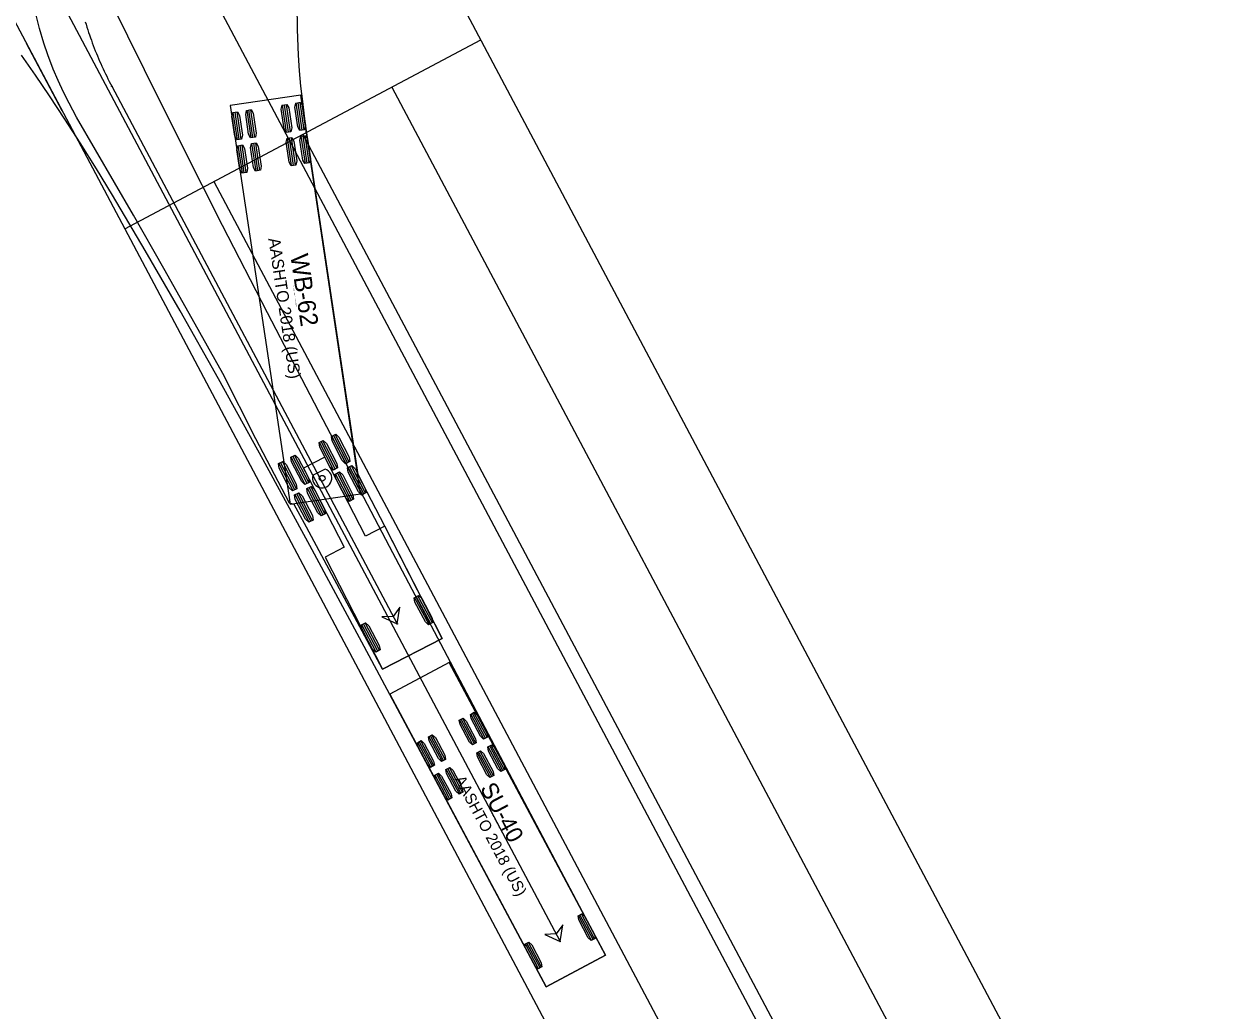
# Model space of a CAD drawing. Extents: x 2297881 to 2300600, y 559917 to 564426.
# Drawn here: x 2299397.2 to 2299541.4, y 561683.1 to 561800.6 of the extents above; entities that cross this region are included whole.
import ezdxf

# ---------------------------------------------------------------- set-up
doc = ezdxf.new("R2010")
doc.units = 0
for name, color, linetype in [('GE_X_Alignment', 7, 'Continuous'), ('PM_P_CL_Pass_Proh_Lt', 7, 'Continuous'), ('PM_P_Dotted_Line', 7, 'Continuous'), ('PM_P_Edge_Line', 7, 'Continuous'), ('PM_P_Lane_Line', 7, 'Continuous'), ('SC_Scratch1', 7, 'Continuous'), ('SN_X_Public', 7, 'Continuous'), ('SV_X_Control_Cells_Found', 7, 'Continuous')]:
    doc.layers.add(name, color=color, linetype=linetype)

msp = doc.modelspace()

# ---------------------------------------------------------------- linework, layer by layer
at = {"layer": 'GE_X_Alignment'}
msp.add_line((2299396.64, 561847.4), (2299991.21, 560726.85), dxfattribs=at)
at = {"layer": 'PM_P_CL_Pass_Proh_Lt'}
msp.add_line((2299430.41, 561787.49), (2299568.68, 561526.9), dxfattribs=at)
at = {"layer": 'PM_P_Dotted_Line'}
msp.add_line((2299441.01, 561793.11), (2299579.28, 561532.52), dxfattribs=at)
at = {"layer": 'PM_P_Edge_Line'}
for p, q in [((2299407.66, 561793.21), (2299441.64, 561729.21)), ((2299430.18, 561792.17), (2299421.77, 561790.91)), ((2299421.77, 561790.91), (2299428.88, 561743.44)), ((2299428.48, 561787.72), (2299427.99, 561790.99)), ((2299428.71, 561787.76), (2299428.22, 561791.02)), ((2299428.94, 561787.79), (2299428.45, 561791.05)), ((2299430.11, 561787.97), (2299429.63, 561791.23)), ((2299430.34, 561788), (2299429.85, 561791.26)), ((2299430.57, 561788.03), (2299430.08, 561791.3)), ((2299437.29, 561744.7), (2299430.18, 561792.17)), ((2299422.61, 561786.84), (2299422.13, 561790.11)), ((2299422.84, 561786.88), (2299422.35, 561790.14)), ((2299423.07, 561786.91), (2299422.58, 561790.18)), ((2299424.25, 561787.09), (2299423.76, 561790.35)), ((2299424.47, 561787.12), (2299423.98, 561790.39)), ((2299424.7, 561787.16), (2299424.21, 561790.42)), ((2299425.29, 561783.2), (2299424.8, 561786.46)), ((2299429.07, 561783.77), (2299428.59, 561787.03)), ((2299429.3, 561783.8), (2299428.81, 561787.06)), ((2299429.53, 561783.83), (2299429.04, 561787.1)), ((2299430.71, 561784.01), (2299430.22, 561787.27)), ((2299430.93, 561784.04), (2299430.44, 561787.31)), ((2299431.16, 561784.08), (2299430.67, 561787.34)), ((2299423.21, 561782.89), (2299422.72, 561786.15)), ((2299423.43, 561782.92), (2299422.94, 561786.19)), ((2299423.66, 561782.96), (2299423.17, 561786.22)), ((2299424.84, 561783.13), (2299424.35, 561786.4)), ((2299425.06, 561783.17), (2299424.58, 561786.43)), ((2299434.07, 561747.54), (2299432.39, 561750.8)), ((2299434.27, 561747.65), (2299432.59, 561750.91)), ((2299434.48, 561747.75), (2299432.8, 561751.01)), ((2299435.54, 561748.3), (2299433.86, 561751.56)), ((2299435.74, 561748.4), (2299434.06, 561751.66)), ((2299435.94, 561748.51), (2299434.26, 561751.77)), ((2299430.7, 561745.81), (2299429.03, 561749.07)), ((2299430.91, 561745.92), (2299429.23, 561749.18)), ((2299431.11, 561746.02), (2299429.43, 561749.28)), ((2299433.03, 561749.07), (2299430.48, 561747.76)), ((2299437.88, 561739.64), (2299433.03, 561749.07)), ((2299429.24, 561745.06), (2299427.56, 561748.32)), ((2299429.44, 561745.16), (2299427.76, 561748.42)), ((2299429.64, 561745.27), (2299427.97, 561748.53)), ((2299430.48, 561747.76), (2299435.33, 561738.33)), ((2299433.06, 561747.63), (2299431.62, 561746.89)), ((2299437.46, 561744.56), (2299435.78, 561747.82)), ((2299437.66, 561744.67), (2299435.98, 561747.93)), ((2299437.86, 561744.77), (2299436.19, 561748.03)), ((2299435.99, 561743.81), (2299434.31, 561747.07)), ((2299436.19, 561743.91), (2299434.52, 561747.17)), ((2299436.4, 561744.02), (2299434.72, 561747.28)), ((2299428.88, 561743.44), (2299437.29, 561744.7)), ((2299431.36, 561741.43), (2299429.69, 561744.69)), ((2299431.57, 561741.53), (2299429.89, 561744.79)), ((2299432.63, 561742.08), (2299430.95, 561745.34)), ((2299432.83, 561742.18), (2299431.15, 561745.44)), ((2299433.03, 561742.29), (2299431.36, 561745.55)), ((2299437.29, 561744.7), (2299437.29, 561744.7)), ((2299431.16, 561741.32), (2299429.48, 561744.58)), ((2299440.16, 561740.82), (2299437.88, 561739.64)), ((2299447.02, 561727.48), (2299440.16, 561740.82)), ((2299435.33, 561738.33), (2299433.05, 561737.16)), ((2299433.05, 561737.16), (2299439.91, 561723.82)), ((2299445.44, 561729.11), (2299443.72, 561732.34)), ((2299445.64, 561729.21), (2299443.92, 561732.45)), ((2299445.84, 561729.32), (2299444.12, 561732.56)), ((2299439.15, 561725.85), (2299437.43, 561729.09)), ((2299439.35, 561725.96), (2299437.63, 561729.2)), ((2299439.55, 561726.07), (2299437.83, 561729.31)), ((2299439.91, 561723.82), (2299447.02, 561727.48)), ((2299447.02, 561727.48), (2299447.02, 561727.48))]:
    msp.add_line(p, q, dxfattribs=at)
for points in [[(2299429.7, 561803.02), (2299429.72, 561799.96), (2299429.86, 561796.9), (2299429.99, 561795.07), (2299430.15, 561793.24), (2299430.35, 561791.41), (2299430.66, 561788.97), (2299436.96, 561746.97), (2299440.14, 561740.86), (2299447.02, 561727.48), (2299439.91, 561723.82), (2299430.85, 561740.71), (2299429.38, 561743.43), (2299428.81, 561743.58), (2299424.82, 561751.25), (2299420.87, 561759.02), (2299417.24, 561765.54), (2299413.87, 561771.51), (2299410.23, 561777.85), (2299403.47, 561789.53), (2299402.56, 561791.19), (2299401.89, 561792.53), (2299401.27, 561793.89), (2299400.69, 561795.25), (2299400.04, 561796.97), (2299399.57, 561798.35), (2299399.05, 561800.1), (2299398.6, 561801.85)], [(2299404.49, 561800.9), (2299404.59, 561800.59), (2299404.69, 561800.27), (2299404.79, 561799.95), (2299404.89, 561799.63), (2299405, 561799.32), (2299405.11, 561799), (2299405.22, 561798.69), (2299405.33, 561798.38), (2299405.45, 561798.06), (2299405.57, 561797.75), (2299405.69, 561797.44), (2299405.82, 561797.13), (2299405.94, 561796.82), (2299406.07, 561796.52), (2299406.2, 561796.21), (2299406.34, 561795.91), (2299406.48, 561795.6), (2299406.61, 561795.3), (2299406.76, 561795), (2299406.9, 561794.7), (2299407.05, 561794.4), (2299407.2, 561794.1), (2299407.35, 561793.8), (2299407.5, 561793.51), (2299407.66, 561793.21)], [(2299441.64, 561729.21), (2299441.97, 561731.18), (2299441.17, 561730.09), (2299439.82, 561730.04), (2299441.64, 561729.21)]]:
    msp.add_lwpolyline(points, dxfattribs=at)
for points in [[(2299428.99, 561787.8), (2299428.43, 561787.71), (2299428.19, 561788.15), (2299427.84, 561790.5), (2299427.94, 561790.98), (2299428.5, 561791.06), (2299428.74, 561790.63), (2299429.09, 561788.28)], [(2299430.62, 561788.04), (2299430.06, 561787.96), (2299429.82, 561788.39), (2299429.47, 561790.74), (2299429.57, 561791.22), (2299430.14, 561791.31), (2299430.37, 561790.87), (2299430.73, 561788.53)], [(2299423.12, 561786.92), (2299422.56, 561786.84), (2299422.32, 561787.27), (2299421.97, 561789.62), (2299422.07, 561790.1), (2299422.64, 561790.18), (2299422.87, 561789.75), (2299423.23, 561787.4)], [(2299424.76, 561787.16), (2299424.19, 561787.08), (2299423.95, 561787.51), (2299423.6, 561789.86), (2299423.7, 561790.34), (2299424.27, 561790.43), (2299424.51, 561790), (2299424.86, 561787.65)], [(2299425.35, 561783.21), (2299424.78, 561783.12), (2299424.54, 561783.56), (2299424.19, 561785.91), (2299424.29, 561786.39), (2299424.86, 561786.47), (2299425.1, 561786.04), (2299425.45, 561783.69)], [(2299429.58, 561783.84), (2299429.02, 561783.76), (2299428.78, 561784.19), (2299428.43, 561786.54), (2299428.53, 561787.02), (2299429.1, 561787.11), (2299429.33, 561786.67), (2299429.69, 561784.32)], [(2299431.22, 561784.09), (2299430.65, 561784), (2299430.41, 561784.43), (2299430.06, 561786.78), (2299430.16, 561787.27), (2299430.73, 561787.35), (2299430.97, 561786.92), (2299431.32, 561784.57)], [(2299423.72, 561782.96), (2299423.15, 561782.88), (2299422.91, 561783.31), (2299422.56, 561785.66), (2299422.66, 561786.14), (2299423.23, 561786.23), (2299423.47, 561785.8), (2299423.82, 561783.45)], [(2299434.53, 561747.78), (2299434.02, 561747.52), (2299433.63, 561747.89), (2299432.42, 561750.24), (2299432.34, 561750.78), (2299432.85, 561751.04), (2299433.24, 561750.66), (2299434.44, 561748.31)], [(2299435.99, 561748.53), (2299435.48, 561748.27), (2299435.1, 561748.65), (2299433.89, 561751), (2299433.81, 561751.53), (2299434.32, 561751.79), (2299434.7, 561751.42), (2299435.91, 561749.07)], [(2299431.16, 561746.05), (2299430.65, 561745.79), (2299430.27, 561746.16), (2299429.06, 561748.51), (2299428.98, 561749.05), (2299429.48, 561749.31), (2299429.87, 561748.93), (2299431.08, 561746.58)], [(2299429.7, 561745.29), (2299429.19, 561745.03), (2299428.8, 561745.41), (2299427.59, 561747.76), (2299427.51, 561748.29), (2299428.02, 561748.55), (2299428.41, 561748.17), (2299429.61, 561745.83)], [(2299437.92, 561744.8), (2299437.41, 561744.54), (2299437.02, 561744.91), (2299435.81, 561747.26), (2299435.73, 561747.8), (2299436.24, 561748.06), (2299436.63, 561747.68), (2299437.83, 561745.33)], [(2299436.45, 561744.04), (2299435.94, 561743.78), (2299435.55, 561744.16), (2299434.34, 561746.51), (2299434.26, 561747.04), (2299434.77, 561747.3), (2299435.16, 561746.93), (2299436.37, 561744.58)], [(2299431.62, 561741.56), (2299431.11, 561741.3), (2299430.72, 561741.67), (2299429.51, 561744.02), (2299429.43, 561744.56), (2299429.94, 561744.82), (2299430.33, 561744.44), (2299431.54, 561742.09)], [(2299433.08, 561742.31), (2299432.58, 561742.05), (2299432.19, 561742.43), (2299430.98, 561744.78), (2299430.9, 561745.31), (2299431.41, 561745.57), (2299431.79, 561745.2), (2299433, 561742.85)], [(2299445.89, 561729.35), (2299445.39, 561729.08), (2299445, 561729.45), (2299443.76, 561731.78), (2299443.67, 561732.32), (2299444.18, 561732.59), (2299444.57, 561732.21), (2299445.81, 561729.88)], [(2299441.64, 561729.21), (2299441.97, 561731.18), (2299441.17, 561730.09), (2299439.82, 561730.04)], [(2299439.6, 561726.1), (2299439.1, 561725.83), (2299438.7, 561726.2), (2299437.47, 561728.53), (2299437.38, 561729.07), (2299437.88, 561729.33), (2299438.28, 561728.96), (2299439.51, 561726.63)]]:
    msp.add_lwpolyline(points, close=True, dxfattribs=at)
for centre, radius in [((2299407.66, 561793.21), 0.0417), ((2299432.71, 561746.54), 0.34), ((2299441.64, 561729.21), 0.0417)]:
    msp.add_circle(centre, radius, dxfattribs=at)
msp.add_arc((2299432.71, 561746.54), 1.14, 162.2344, 72.2344, dxfattribs=at)
at = {"layer": 'PM_P_Lane_Line'}
for p, q in [((2299419.39, 561859.47), (2299927.35, 560902.13)), ((2299376.99, 561836.97), (2299547.48, 561515.65))]:
    msp.add_line(p, q, dxfattribs=at)
at = {"layer": 'SC_Scratch1'}
for p, q in [((2299401.75, 561790.3), (2299397.49, 561798.32)), ((2299409.21, 561776.24), (2299451.61, 561798.74))]:
    msp.add_line(p, q, dxfattribs=at)
at = {"layer": 'SN_X_Public'}
for p, q in [((2299397.07, 561811.91), (2299461.04, 561691.4)), ((2299447.84, 561724.6), (2299440.78, 561720.83)), ((2299466.45, 561689.76), (2299447.84, 561724.6)), ((2299440.78, 561720.83), (2299459.39, 561685.99)), ((2299450.66, 561714.81), (2299449.09, 561717.75)), ((2299450.84, 561714.9), (2299449.27, 561717.85)), ((2299451.03, 561715), (2299449.46, 561717.94)), ((2299451.98, 561715.51), (2299450.41, 561718.45)), ((2299452.17, 561715.61), (2299450.6, 561718.55)), ((2299452.35, 561715.71), (2299450.78, 561718.65)), ((2299447.17, 561712.94), (2299445.6, 561715.88)), ((2299447.35, 561713.04), (2299445.78, 561715.98)), ((2299445.66, 561712.14), (2299444.09, 561715.08)), ((2299445.85, 561712.24), (2299444.28, 561715.18)), ((2299446.03, 561712.33), (2299444.46, 561715.27)), ((2299446.99, 561712.84), (2299445.42, 561715.78)), ((2299454.06, 561711.63), (2299452.49, 561714.57)), ((2299454.24, 561711.73), (2299452.67, 561714.67)), ((2299454.42, 561711.83), (2299452.85, 561714.77)), ((2299452.73, 561710.93), (2299451.16, 561713.87)), ((2299452.92, 561711.02), (2299451.35, 561713.96)), ((2299453.1, 561711.12), (2299451.53, 561714.06)), ((2299449.06, 561708.96), (2299447.49, 561711.9)), ((2299449.24, 561709.06), (2299447.67, 561712)), ((2299449.43, 561709.16), (2299447.86, 561712.1)), ((2299447.73, 561708.26), (2299446.16, 561711.2)), ((2299447.92, 561708.35), (2299446.35, 561711.29)), ((2299448.1, 561708.45), (2299446.53, 561711.39)), ((2299464.79, 561691.52), (2299463.23, 561694.46)), ((2299464.98, 561691.62), (2299463.42, 561694.56)), ((2299465.16, 561691.71), (2299463.6, 561694.66)), ((2299458.47, 561688.14), (2299456.91, 561691.09)), ((2299458.66, 561688.24), (2299457.09, 561691.19)), ((2299458.84, 561688.34), (2299457.28, 561691.28)), ((2299459.39, 561685.99), (2299466.45, 561689.76)), ((2299466.45, 561689.76), (2299466.45, 561689.76))]:
    msp.add_line(p, q, dxfattribs=at)
for points in [[(2299403.52, 561811.37), (2299411.5, 561795.2), (2299415.98, 561786.22), (2299420.81, 561776.67), (2299426.16, 561766.27), (2299432.78, 561753.53), (2299440.69, 561738.45), (2299450.66, 561719.55), (2299464.41, 561693.6), (2299466.45, 561689.76), (2299459.39, 561685.99), (2299437.73, 561726.5), (2299431.26, 561738.52), (2299425.69, 561748.75), (2299420.37, 561758.36), (2299415.8, 561766.47), (2299411.64, 561773.67), (2299407.73, 561780.25), (2299405.82, 561783.37), (2299403.88, 561786.47), (2299402.08, 561789.28), (2299400.25, 561792.06), (2299398.57, 561794.54), (2299396.91, 561796.93)], [(2299461.04, 561691.4), (2299461.37, 561693.37), (2299460.57, 561692.28), (2299459.22, 561692.23), (2299461.04, 561691.4)]]:
    msp.add_lwpolyline(points, dxfattribs=at)
for points in [[(2299451.07, 561715.03), (2299450.62, 561714.78), (2299450.26, 561715.12), (2299449.13, 561717.24), (2299449.04, 561717.72), (2299449.5, 561717.97), (2299449.86, 561717.63), (2299450.99, 561715.51)], [(2299452.4, 561715.73), (2299451.94, 561715.49), (2299451.58, 561715.83), (2299450.45, 561717.94), (2299450.37, 561718.43), (2299450.83, 561718.67), (2299451.18, 561718.34), (2299452.32, 561716.22)], [(2299447.4, 561713.06), (2299446.94, 561712.82), (2299446.58, 561713.16), (2299445.45, 561715.27), (2299445.37, 561715.76), (2299445.83, 561716), (2299446.19, 561715.67), (2299447.32, 561713.55)], [(2299446.08, 561712.36), (2299445.62, 561712.11), (2299445.26, 561712.45), (2299444.13, 561714.57), (2299444.05, 561715.05), (2299444.5, 561715.3), (2299444.86, 561714.96), (2299445.99, 561712.84)], [(2299454.47, 561711.85), (2299454.01, 561711.61), (2299453.65, 561711.95), (2299452.52, 561714.06), (2299452.44, 561714.55), (2299452.9, 561714.79), (2299453.26, 561714.46), (2299454.39, 561712.34)], [(2299453.15, 561711.15), (2299452.69, 561710.9), (2299452.33, 561711.24), (2299451.2, 561713.36), (2299451.12, 561713.84), (2299451.58, 561714.09), (2299451.93, 561713.75), (2299453.06, 561711.63)], [(2299449.47, 561709.18), (2299449.01, 561708.94), (2299448.65, 561709.28), (2299447.52, 561711.39), (2299447.44, 561711.88), (2299447.9, 561712.12), (2299448.26, 561711.79), (2299449.39, 561709.67)], [(2299448.15, 561708.48), (2299447.69, 561708.23), (2299447.33, 561708.57), (2299446.2, 561710.69), (2299446.12, 561711.17), (2299446.58, 561711.42), (2299446.94, 561711.08), (2299448.07, 561708.96)], [(2299465.21, 561691.74), (2299464.75, 561691.49), (2299464.39, 561691.83), (2299463.27, 561693.95), (2299463.19, 561694.44), (2299463.64, 561694.68), (2299464, 561694.34), (2299465.13, 561692.22)], [(2299461.04, 561691.4), (2299461.37, 561693.37), (2299460.57, 561692.28), (2299459.22, 561692.23)], [(2299458.89, 561688.36), (2299458.43, 561688.12), (2299458.07, 561688.46), (2299456.94, 561690.58), (2299456.86, 561691.06), (2299457.32, 561691.31), (2299457.68, 561690.97), (2299458.8, 561688.85)]]:
    msp.add_lwpolyline(points, close=True, dxfattribs=at)
msp.add_circle((2299461.04, 561691.4), 0.0417, dxfattribs=at)
at = {"layer": 'SV_X_Control_Cells_Found'}
msp.add_line((2299419.81, 561781.86), (2299558.08, 561521.28), dxfattribs=at)

# ---------------------------------------------------------------- texts
at = {"layer": 'PM_P_Edge_Line'}
for s, height, p in [('AASHTO 2018 (US)', 1.4167, (2299426.29, 561775.07)), ('WB-62', 2.125, (2299428.91, 561773.09)), ('(c) 2021 Transoft Solutions, Inc. All rights reserved.', 0.085, (2299429.23, 561769.51))]:
    msp.add_text(s, height=height, rotation=278.513, dxfattribs=at).set_placement(p)
at = {"layer": 'SN_X_Public'}
for s, height, p in [('AASHTO 2018 (US)', 1.3333, (2299448.45, 561710.71)), ('SU-40', 2, (2299451.47, 561709.65)), ('(c) 2021 Transoft Solutions, Inc. All rights reserved.', 0.08, (2299452.81, 561706.71))]:
    msp.add_text(s, height=height, rotation=298.105, dxfattribs=at).set_placement(p)

doc.saveas('drawing.dxf')
